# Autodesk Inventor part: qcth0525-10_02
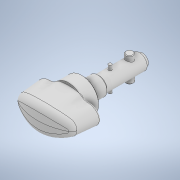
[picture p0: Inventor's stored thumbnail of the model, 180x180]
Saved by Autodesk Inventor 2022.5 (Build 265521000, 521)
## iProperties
Created: 2022-02
Part Number: qcth0525-10_02
Material: 一般
Document SubType Name: Modeling
Designer: ImaoCorp
Density: 1 g/cm^3
Appearance: 既定
Author: ImaoCorp
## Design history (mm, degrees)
feature "qcth0525-10_02"
node "ソリッド1"
